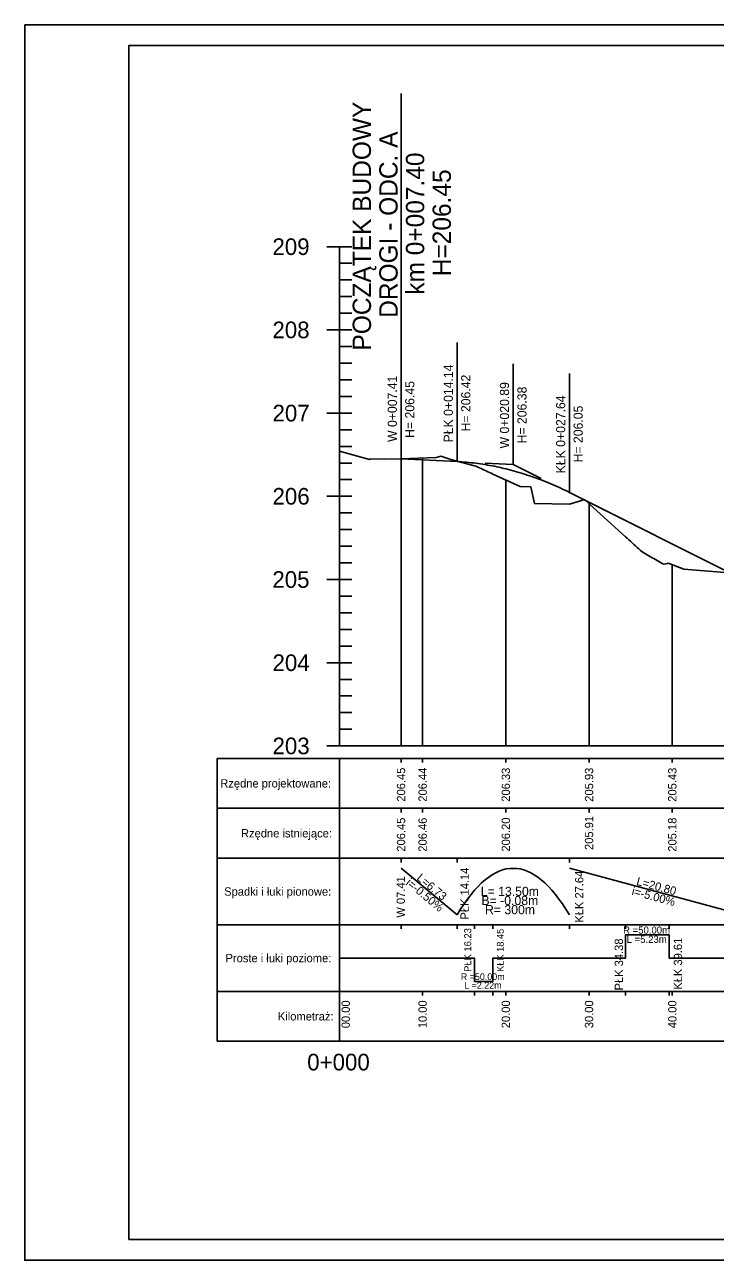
# Model space of a CAD drawing. Extents: x 6512707 to 6513007, y 6022307 to 6022469.
# Drawn here: x 6512706.6 to 6512789.6, y 6022306.7 to 6022455.2 of the extents above; entities that cross this region are included whole.
import ezdxf

# ---------------------------------------------------------------- set-up
doc = ezdxf.new("R2010")
doc.units = 0
for name, color, linetype in [('1', 7, 'Continuous'), ('31', 7, 'Continuous'), ('42', 7, 'Continuous'), ('54', 7, 'Continuous'), ('Level 20', 7, 'Continuous'), ('maxp_opisy', 7, 'Continuous'), ('maxp_ramka_2', 7, 'Continuous')]:
    doc.layers.add(name, color=color, linetype=linetype)

msp = doc.modelspace()

# ---------------------------------------------------------------- linework, layer by layer
for p, q in [((6512751.83, 6022403.07), (6512758.56, 6022402.73)), ((6512751.83, 6022403.07), (6512758.56, 6022402.73)), ((6512772.06, 6022399.02), (6512792.86, 6022388.62)), ((6512772.06, 6022399.02), (6512792.86, 6022388.62))]:
    msp.add_line(p, q)
for points in [[(6512758.56, 6022402.73), (6512758.84, 6022402.71), (6512759.12, 6022402.7), (6512759.4, 6022402.68), (6512759.69, 6022402.65), (6512759.97, 6022402.63), (6512760.25, 6022402.6), (6512760.53, 6022402.57), (6512760.81, 6022402.53), (6512761.09, 6022402.5), (6512761.37, 6022402.46), (6512761.65, 6022402.42), (6512761.94, 6022402.37), (6512762.22, 6022402.32), (6512762.5, 6022402.28), (6512762.78, 6022402.22), (6512763.06, 6022402.17), (6512763.34, 6022402.11), (6512763.62, 6022402.05), (6512763.9, 6022401.99), (6512764.18, 6022401.92), (6512764.47, 6022401.85), (6512764.75, 6022401.78), (6512765.03, 6022401.71), (6512765.59, 6022401.55), (6512765.87, 6022401.47), (6512766.15, 6022401.39), (6512766.43, 6022401.3), (6512766.72, 6022401.21), (6512767, 6022401.12), (6512767.28, 6022401.03), (6512767.56, 6022400.93), (6512767.84, 6022400.83), (6512768.12, 6022400.73), (6512768.4, 6022400.62), (6512768.68, 6022400.52), (6512768.96, 6022400.41), (6512769.25, 6022400.29), (6512769.53, 6022400.18), (6512769.81, 6022400.06), (6512770.09, 6022399.94), (6512770.37, 6022399.81), (6512770.65, 6022399.69), (6512770.93, 6022399.56), (6512771.21, 6022399.43), (6512771.5, 6022399.29), (6512771.78, 6022399.16), (6512772.06, 6022399.02)], [(6512758.56, 6022402.73), (6512758.84, 6022402.71), (6512759.12, 6022402.7), (6512759.4, 6022402.68), (6512759.69, 6022402.65), (6512759.97, 6022402.63), (6512760.25, 6022402.6), (6512760.53, 6022402.57), (6512760.81, 6022402.53), (6512761.09, 6022402.5), (6512761.37, 6022402.46), (6512761.65, 6022402.42), (6512761.94, 6022402.37), (6512762.22, 6022402.32), (6512762.5, 6022402.28), (6512762.78, 6022402.22), (6512763.06, 6022402.17), (6512763.34, 6022402.11), (6512763.62, 6022402.05), (6512763.9, 6022401.99), (6512764.18, 6022401.92), (6512764.47, 6022401.85), (6512764.75, 6022401.78), (6512765.03, 6022401.71), (6512765.59, 6022401.55), (6512765.87, 6022401.47), (6512766.15, 6022401.39), (6512766.43, 6022401.3), (6512766.72, 6022401.21), (6512767, 6022401.12), (6512767.28, 6022401.03), (6512767.56, 6022400.93), (6512767.84, 6022400.83), (6512768.12, 6022400.73), (6512768.4, 6022400.62), (6512768.68, 6022400.52), (6512768.96, 6022400.41), (6512769.25, 6022400.29), (6512769.53, 6022400.18), (6512769.81, 6022400.06), (6512770.09, 6022399.94), (6512770.37, 6022399.81), (6512770.65, 6022399.69), (6512770.93, 6022399.56), (6512771.21, 6022399.43), (6512771.5, 6022399.29), (6512771.78, 6022399.16), (6512772.06, 6022399.02)], [(6512751.83, 6022353.86), (6512758.56, 6022348.26)], [(6512758.56, 6022348.26), (6512758.98, 6022348.94), (6512759.4, 6022349.57), (6512759.83, 6022350.16), (6512760.25, 6022350.71), (6512760.67, 6022351.21), (6512761.09, 6022351.67), (6512761.51, 6022352.09), (6512761.94, 6022352.46), (6512762.36, 6022352.79), (6512762.78, 6022353.07), (6512763.2, 6022353.31), (6512763.62, 6022353.51), (6512764.04, 6022353.66), (6512764.47, 6022353.77), (6512764.89, 6022353.84), (6512765.73, 6022353.84), (6512766.15, 6022353.77), (6512766.57, 6022353.66), (6512767, 6022353.51), (6512767.42, 6022353.31), (6512767.84, 6022353.07), (6512768.26, 6022352.79), (6512768.68, 6022352.46), (6512769.11, 6022352.09), (6512769.53, 6022351.67), (6512769.95, 6022351.21), (6512770.37, 6022350.71), (6512770.79, 6022350.16), (6512771.21, 6022349.57), (6512771.64, 6022348.94), (6512772.06, 6022348.26)], [(6512772.06, 6022353.86), (6512792.86, 6022348.26)], [(6512744.42, 6022343.06), (6512760.65, 6022343.06), (6512760.65, 6022340.26), (6512762.86, 6022340.26), (6512762.86, 6022343.06), (6512778.8, 6022343.06), (6512778.8, 6022345.86), (6512784.03, 6022345.86), (6512784.03, 6022343.06), (6512812.66, 6022343.06), (6512812.66, 6022340.26), (6512834.1, 6022340.26), (6512834.1, 6022343.06), (6512900.39, 6022343.06), (6512900.39, 6022340.26), (6512925.12, 6022340.26), (6512925.12, 6022343.06), (6512943.18, 6022343.06), (6512943.18, 6022343.06), (6512944.85, 6022343.06), (6512944.85, 6022343.06), (6512949.83, 6022343.06)]]:
    msp.add_lwpolyline(points)
at = {"layer": '1'}
for p, q in [((6512742.92, 6022428.56), (6512745.92, 6022428.56)), ((6512742.92, 6022428.56), (6512745.92, 6022428.56)), ((6512744.42, 6022368.56), (6512744.42, 6022428.56)), ((6512744.42, 6022426.56), (6512745.92, 6022426.56)), ((6512744.42, 6022424.56), (6512745.92, 6022424.56)), ((6512744.42, 6022422.56), (6512745.92, 6022422.56)), ((6512744.42, 6022420.56), (6512745.92, 6022420.56)), ((6512742.92, 6022418.56), (6512745.92, 6022418.56)), ((6512744.42, 6022416.56), (6512745.92, 6022416.56)), ((6512744.42, 6022414.56), (6512745.92, 6022414.56)), ((6512744.42, 6022412.56), (6512745.92, 6022412.56)), ((6512744.42, 6022410.56), (6512745.92, 6022410.56)), ((6512742.92, 6022408.56), (6512745.92, 6022408.56)), ((6512744.42, 6022406.56), (6512745.92, 6022406.56)), ((6512744.42, 6022404.56), (6512745.92, 6022404.56)), ((6512754.42, 6022368.56), (6512754.42, 6022403.19)), ((6512744.42, 6022402.56), (6512745.92, 6022402.56)), ((6512761.94, 6022402.56), (6512765.31, 6022402.39)), ((6512765.31, 6022402.39), (6512768.68, 6022400.71)), ((6512744.42, 6022400.56), (6512745.92, 6022400.56)), ((6512764.42, 6022368.56), (6512764.42, 6022400.53)), ((6512742.92, 6022398.56), (6512745.92, 6022398.56)), ((6512774.42, 6022368.56), (6512774.42, 6022397.7)), ((6512744.42, 6022396.56), (6512745.92, 6022396.56)), ((6512744.42, 6022394.56), (6512745.92, 6022394.56)), ((6512744.42, 6022392.56), (6512745.92, 6022392.56)), ((6512744.42, 6022390.56), (6512745.92, 6022390.56)), ((6512784.42, 6022368.56), (6512784.42, 6022390.34)), ((6512742.92, 6022388.56), (6512745.92, 6022388.56)), ((6512744.42, 6022386.56), (6512745.92, 6022386.56)), ((6512744.42, 6022384.56), (6512745.92, 6022384.56)), ((6512744.42, 6022382.56), (6512745.92, 6022382.56)), ((6512744.42, 6022380.56), (6512745.92, 6022380.56)), ((6512742.92, 6022378.56), (6512745.92, 6022378.56)), ((6512744.42, 6022376.56), (6512745.92, 6022376.56)), ((6512744.42, 6022374.56), (6512745.92, 6022374.56)), ((6512744.42, 6022372.56), (6512745.92, 6022372.56)), ((6512744.42, 6022370.56), (6512745.92, 6022370.56)), ((6512744.42, 6022368.56), (6512744.42, 6022370.56)), ((6512742.92, 6022368.56), (6512745.92, 6022368.56)), ((6512744.42, 6022368.56), (6512954.42, 6022368.56)), ((6512754.42, 6022368.56), (6512754.42, 6022369.56)), ((6512764.42, 6022368.56), (6512764.42, 6022369.56)), ((6512774.42, 6022368.56), (6512774.42, 6022369.56)), ((6512784.42, 6022368.56), (6512784.42, 6022369.56))]:
    msp.add_line(p, q, dxfattribs=at)
msp.add_lwpolyline([(6512744.42, 6022403.99), (6512748.04, 6022402.99), (6512748.18, 6022403.07), (6512749.85, 6022403.04), (6512751.8, 6022403.07), (6512756.06, 6022403.24), (6512756.62, 6022403.38), (6512757.92, 6022402.95), (6512760.65, 6022402.23), (6512760.81, 6022402.19), (6512760.85, 6022402.17), (6512761.05, 6022402.08), (6512761.25, 6022401.99), (6512761.45, 6022401.89), (6512761.66, 6022401.8), (6512761.86, 6022401.71), (6512762.06, 6022401.62), (6512762.26, 6022401.52), (6512762.46, 6022401.43), (6512762.66, 6022401.34), (6512762.86, 6022401.24), (6512766.15, 6022399.72), (6512767.42, 6022399.68), (6512767.85, 6022397.7), (6512772.07, 6022397.63), (6512773.9, 6022398.17), (6512774.49, 6022397.63), (6512778.8, 6022393.69), (6512779, 6022393.51), (6512779.2, 6022393.33), (6512779.4, 6022393.15), (6512779.6, 6022392.96), (6512779.81, 6022392.78), (6512780.01, 6022392.6), (6512780.21, 6022392.42), (6512780.41, 6022392.24), (6512780.61, 6022392.06), (6512780.75, 6022391.94), (6512780.81, 6022391.9), (6512781.01, 6022391.78), (6512781.21, 6022391.66), (6512781.41, 6022391.54), (6512781.61, 6022391.42), (6512781.82, 6022391.3), (6512782.02, 6022391.18), (6512782.22, 6022391.07), (6512782.42, 6022390.95), (6512782.62, 6022390.84), (6512782.82, 6022390.72), (6512783.02, 6022390.61), (6512783.22, 6022390.5), (6512783.41, 6022390.39), (6512783.42, 6022390.4), (6512783.62, 6022390.45), (6512783.83, 6022390.5), (6512783.94, 6022390.53), (6512784.03, 6022390.49), (6512785.79, 6022389.82), (6512792.74, 6022389.23)], dxfattribs=at)
at = {"layer": '42'}
for p, q in [((6512751.83, 6022368.57), (6512751.83, 6022446.98)), ((6512758.56, 6022402.73), (6512758.56, 6022417.03)), ((6512751.83, 6022403.07), (6512751.83, 6022415.17)), ((6512751.83, 6022403.06), (6512751.83, 6022415.16)), ((6512765.31, 6022402.39), (6512765.31, 6022414.49)), ((6512772.06, 6022399.02), (6512772.06, 6022413.32)), ((6512751.83, 6022403.07), (6512758.56, 6022402.73)), ((6512772.06, 6022399.02), (6512792.86, 6022388.62))]:
    msp.add_line(p, q, dxfattribs=at)
msp.add_lwpolyline([(6512758.56, 6022402.73), (6512758.84, 6022402.71), (6512759.12, 6022402.7), (6512759.4, 6022402.68), (6512759.69, 6022402.65), (6512759.97, 6022402.63), (6512760.25, 6022402.6), (6512760.53, 6022402.57), (6512760.81, 6022402.53), (6512761.09, 6022402.5), (6512761.37, 6022402.46), (6512761.65, 6022402.42), (6512761.94, 6022402.37), (6512762.22, 6022402.32), (6512762.5, 6022402.28), (6512762.78, 6022402.22), (6512763.06, 6022402.17), (6512763.34, 6022402.11), (6512763.62, 6022402.05), (6512763.9, 6022401.99), (6512764.18, 6022401.92), (6512764.47, 6022401.85), (6512764.75, 6022401.78), (6512765.03, 6022401.71), (6512765.59, 6022401.55), (6512765.87, 6022401.47), (6512766.15, 6022401.39), (6512766.43, 6022401.3), (6512766.72, 6022401.21), (6512767, 6022401.12), (6512767.28, 6022401.03), (6512767.56, 6022400.93), (6512767.84, 6022400.83), (6512768.12, 6022400.73), (6512768.4, 6022400.62), (6512768.68, 6022400.52), (6512768.96, 6022400.41), (6512769.25, 6022400.29), (6512769.53, 6022400.18), (6512769.81, 6022400.06), (6512770.09, 6022399.94), (6512770.37, 6022399.81), (6512770.65, 6022399.69), (6512770.93, 6022399.56), (6512771.21, 6022399.43), (6512771.5, 6022399.29), (6512771.78, 6022399.16), (6512772.06, 6022399.02)], dxfattribs=at)
at = {"layer": '54'}
for points in [[(6512744.42, 6022367.06), (6512729.74, 6022367.06), (6512729.74, 6022361.06), (6512744.42, 6022361.06)], [(6512744.42, 6022366.56), (6512744.42, 6022367.06)], [(6512751.83, 6022366.56), (6512751.83, 6022367.06)], [(6512754.42, 6022366.56), (6512754.42, 6022367.06)], [(6512764.42, 6022366.56), (6512764.42, 6022367.06)], [(6512774.42, 6022366.56), (6512774.42, 6022367.06)], [(6512784.42, 6022366.56), (6512784.42, 6022367.06)], [(6512744.42, 6022361.06), (6512729.74, 6022361.06), (6512729.74, 6022355.06), (6512744.42, 6022355.06)], [(6512744.42, 6022360.56), (6512744.42, 6022361.06)], [(6512751.83, 6022360.56), (6512751.83, 6022361.06)], [(6512754.42, 6022360.56), (6512754.42, 6022361.06)], [(6512764.42, 6022360.56), (6512764.42, 6022361.06)], [(6512774.42, 6022360.56), (6512774.42, 6022361.06)], [(6512784.42, 6022360.56), (6512784.42, 6022361.06)], [(6512744.42, 6022355.06), (6512729.74, 6022355.06), (6512729.74, 6022347.06), (6512744.42, 6022347.06)], [(6512751.83, 6022354.56), (6512751.83, 6022355.06)], [(6512758.56, 6022354.56), (6512758.56, 6022355.06)], [(6512772.06, 6022354.56), (6512772.06, 6022355.06)], [(6512744.42, 6022347.06), (6512729.74, 6022347.06), (6512729.74, 6022339.06), (6512744.42, 6022339.06)], [(6512744.42, 6022346.56), (6512744.42, 6022347.06)], [(6512751.83, 6022346.56), (6512751.83, 6022347.06)], [(6512758.56, 6022346.56), (6512758.56, 6022347.06)], [(6512760.65, 6022346.56), (6512760.65, 6022347.06)], [(6512762.86, 6022346.56), (6512762.86, 6022347.06)], [(6512772.06, 6022346.56), (6512772.06, 6022347.06)], [(6512778.8, 6022346.56), (6512778.8, 6022347.06)], [(6512784.03, 6022346.56), (6512784.03, 6022347.06)], [(6512744.42, 6022339.06), (6512729.74, 6022339.06), (6512729.74, 6022333.06), (6512744.42, 6022333.06)], [(6512744.42, 6022338.56), (6512744.42, 6022339.06)], [(6512744.42, 6022338.56), (6512744.42, 6022339.06)], [(6512754.42, 6022338.56), (6512754.42, 6022339.06)], [(6512760.65, 6022338.56), (6512760.65, 6022339.06)], [(6512762.86, 6022338.56), (6512762.86, 6022339.06)], [(6512764.42, 6022338.56), (6512764.42, 6022339.06)], [(6512774.42, 6022338.56), (6512774.42, 6022339.06)], [(6512778.8, 6022338.56), (6512778.8, 6022339.06)], [(6512784.03, 6022338.56), (6512784.03, 6022339.06)], [(6512784.42, 6022338.56), (6512784.42, 6022339.06)]]:
    msp.add_lwpolyline(points, dxfattribs=at)
for points in [[(6512744.42, 6022361.06), (6512954.42, 6022361.06), (6512954.42, 6022367.06), (6512744.42, 6022367.06)], [(6512744.42, 6022355.06), (6512954.42, 6022355.06), (6512954.42, 6022361.06), (6512744.42, 6022361.06)], [(6512744.42, 6022347.06), (6512954.42, 6022347.06), (6512954.42, 6022355.06), (6512744.42, 6022355.06)], [(6512744.42, 6022347.06), (6512729.74, 6022347.06), (6512729.74, 6022347.06)], [(6512744.42, 6022339.06), (6512954.42, 6022339.06), (6512954.42, 6022347.06), (6512744.42, 6022347.06)], [(6512744.42, 6022339.06), (6512729.74, 6022339.06), (6512729.74, 6022339.06)], [(6512744.42, 6022333.06), (6512954.42, 6022333.06), (6512954.42, 6022339.06), (6512744.42, 6022339.06)]]:
    msp.add_lwpolyline(points, close=True, dxfattribs=at)
at = {"layer": 'maxp_ramka_2'}
for points in [[(6512706.62, 6022455.24), (6513006.62, 6022455.24), (6513006.62, 6022306.74), (6512706.62, 6022306.74)], [(6512719.12, 6022309.24), (6512719.12, 6022452.74), (6513004.12, 6022452.74), (6513004.12, 6022309.24)]]:
    msp.add_lwpolyline(points, close=True, dxfattribs=at)

# ---------------------------------------------------------------- texts
at = {"layer": '1'}
for s, height, p in [('209', 2, (6512736.38, 6022427.56)), ('209', 2, (6512736.38, 6022427.56)), ('208', 2, (6512736.38, 6022417.56)), ('207', 2, (6512736.39, 6022407.56)), ('206', 2, (6512736.39, 6022397.56)), ('205', 2, (6512736.37, 6022387.56)), ('204', 2, (6512736.39, 6022377.56)), ('203', 2, (6512736.39, 6022367.56)), (' Rzędne istniejące: ', 1, (6512732.23, 6022357.56)), ('0+000', 2, (6512740.56, 6022329.56))]:
    msp.add_text(s, height=height, dxfattribs=at).set_placement(p)
for s, p in [('206.45', (6512752.33, 6022355.85)), ('206.46', (6512754.92, 6022355.85)), ('206.20', (6512764.92, 6022355.86)), ('205.91', (6512774.92, 6022356.05)), ('205.18', (6512784.92, 6022355.85)), ('PŁK 14.14', (6512759.97, 6022347.69)), ('W 07.41', (6512752.3, 6022347.92)), ('KŁK 27.64', (6512773.74, 6022347.31))]:
    msp.add_text(s, height=1, rotation=90, dxfattribs=at).set_placement(p)
at = {"layer": '31'}
for s, p in [('206.45', (6512752.33, 6022361.86)), ('206.44', (6512754.92, 6022361.86)), ('206.33', (6512764.92, 6022361.85)), ('205.93', (6512774.92, 6022361.85)), ('205.43', (6512784.92, 6022361.85))]:
    msp.add_text(s, height=1, rotation=90, dxfattribs=at).set_placement(p)
msp.add_text(' Rzędne projektowane: ', height=1, dxfattribs=at).set_placement((6512729.74, 6022363.56))
at = {"layer": '42'}
for s, p in [('PŁK 0+014.14', (6512758.06, 6022405.03)), ('H= 206.42', (6512760.16, 6022406.35)), ('W 0+007.41', (6512751.33, 6022405.09)), ('H= 206.45', (6512753.43, 6022405.58)), ('W 0+020.89', (6512764.81, 6022404.31)), ('H= 206.38', (6512766.91, 6022404.91)), ('KŁK 0+027.64', (6512771.56, 6022401.32)), ('H= 206.05', (6512773.66, 6022402.63))]:
    msp.add_text(s, height=1.1, rotation=90, dxfattribs=at).set_placement(p)
for s, p in [('L= 13.50m', (6512761.41, 6022350.53)), ('B= -0.08m', (6512761.49, 6022349.43)), ('R= 300m', (6512761.92, 6022348.33))]:
    msp.add_text(s, height=1.1, dxfattribs=at).set_placement(p)
at = {"layer": '54'}
for s, height, p in [('PŁK 16.23', 0.841, (6512760.26, 6022341.41)), ('KŁK 18.45', 0.828, (6512764.17, 6022341.41)), ('PŁK 34.38', 1, (6512778.5, 6022339.17)), ('KŁK 39.61', 1, (6512785.6, 6022339.26)), ('00.00', 1, (6512745.68, 6022334.63)), ('10.00', 1, (6512754.92, 6022334.63)), ('20.00', 1, (6512764.92, 6022334.63)), ('30.00', 1, (6512774.92, 6022334.63)), ('40.00', 1, (6512784.92, 6022334.63))]:
    msp.add_text(s, height=height, rotation=90, dxfattribs=at).set_placement(p)
for s, height, p in [('R =50.00m', 0.857, (6512778.51, 6022346)), ('L =5.23m', 0.857, (6512778.94, 6022344.89)), (' Proste i łuki poziome: ', 1, (6512730.37, 6022342.56)), ('R =50.00m', 0.801, (6512759.01, 6022340.42)), ('L =2.22m', 0.801, (6512759.42, 6022339.39)), (' Kilometraż: ', 1, (6512736.66, 6022335.56))]:
    msp.add_text(s, height=height, dxfattribs=at).set_placement(p)
at = {"layer": 'Level 20'}
for s, rotation, p in [('i=-0.50%', 320.2327, (6512752.33, 6022351.96)), ('L=6.73', 320.2327, (6512753.63, 6022352.55)), ('L=20.80', 344.9343, (6512780.04, 6022351.86)), ('i=-5.00%', 344.9343, (6512779.48, 6022350.68))]:
    msp.add_text(s, height=1, rotation=rotation, dxfattribs=at).set_placement(p)
msp.add_text(' Spadki i łuki pionowe: ', height=1, dxfattribs=at).set_placement((6512730.21, 6022350.56))
at = {"layer": 'maxp_opisy'}
for s, p in [('POCZĄTEK BUDOWY', (6512748.22, 6022416.08)), ('DROGI - ODC. A', (6512751.42, 6022420.01)), ('km 0+007.40', (6512754.62, 6022422.79)), ('H=206.45', (6512757.82, 6022425.01))]:
    msp.add_text(s, height=2.2, rotation=90.0162, dxfattribs=at).set_placement(p)

doc.saveas('drawing.dxf')
